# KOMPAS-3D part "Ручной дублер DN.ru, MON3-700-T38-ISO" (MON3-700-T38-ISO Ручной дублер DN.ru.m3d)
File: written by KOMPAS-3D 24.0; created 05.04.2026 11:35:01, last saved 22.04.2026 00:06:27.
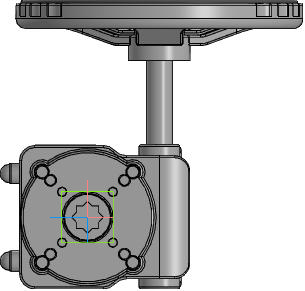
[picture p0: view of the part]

Document properties: Автор: R2D2; Полное имя файла: E:\Работа\Зайцев\Аксессуары для пневмоприводов\Ручной дублер DN.ru\MON3-700-T38-ISO Ручной дублер DN.ru\исходные материалы\MON3-700-T38-ISO Ручной дублер DN.ru.m3d

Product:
- Part/product: Ручной дублер DN.ru  | designation MON3-700-T38-ISO
    Масса: 6.9
    Раздел спецификации: Прочие изделия
    Примечание: D290-00338

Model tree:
1. Операция без истории:1
2. Эскиз:1  (with: Грань.Операция без истории:1, Ребро.Операция без истории:1)
3. Элемент выдавливания:1
     Расстояние 2 = 15
4. Эскиз:2  (with: Грань.Операция без истории:1, Ребро.Операция без истории:1)
5. Элемент выдавливания:2
     Расстояние 2 = 15
6. Массив по концентрической сетке:1  (with: Элемент выдавливания:2, Эскиз:2, Грань.Операция без истории:1)  (4 pattern instances)
     Шаг 2 = 360
7. Эскиз:3  (with: Грань.Операция без истории:1, Ребро.Элемент выдавливания:2)  (labels: Ребро.Элемент выдавливания:2.Экземпляр ( 1, 4 ); Ребро.Элемент выдавливания:2.Экземпляр ( 1, 3 ); Ребро.Элемент выдавливания:2.Экземпляр ( 1, 2 ))
8. Элемент выдавливания:3
     Расстояние 2 = 13
9. Фаска:1  (with: Ребро.Элемент выдавливания:3)
     Угол = 45; Длина 1 = 0.5; Длина 2 = 0.5
10. Элемент выдавливания:4  (with: Грань.Операция без истории:1)
     Расстояние 2 = 3
11. Массив по концентрической сетке:2  (with: Элемент выдавливания:4, Грань.Операция без истории:1)  (4 pattern instances)
     Шаг 2 = 360
12. Элемент выдавливания:5  (with: Грань.Операция без истории:1)
     Расстояние 1 = 1.2

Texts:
  MON3-700-T38-ISO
